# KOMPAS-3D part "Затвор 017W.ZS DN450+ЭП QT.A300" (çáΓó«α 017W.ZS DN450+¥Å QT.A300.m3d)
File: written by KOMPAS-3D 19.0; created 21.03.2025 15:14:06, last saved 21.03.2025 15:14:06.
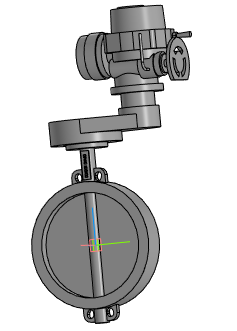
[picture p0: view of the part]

Document properties: Полное имя файла: Затвор 017W.ZS DN450+ЭП QT.A300.a3d

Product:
- Part/product: Затвор 017W.ZS DN450+ЭП QT.A300
    Масса: 337.471

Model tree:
1. Операция без истории:1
